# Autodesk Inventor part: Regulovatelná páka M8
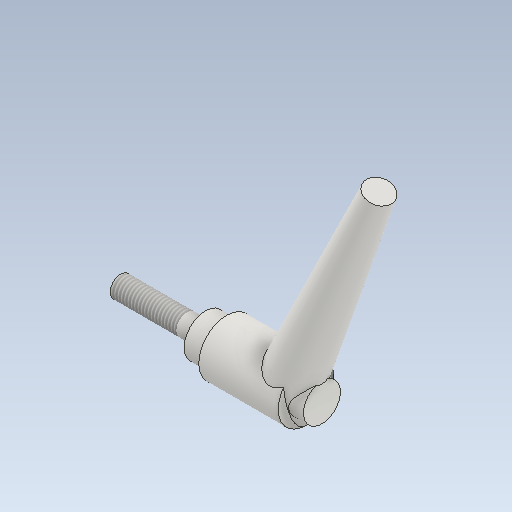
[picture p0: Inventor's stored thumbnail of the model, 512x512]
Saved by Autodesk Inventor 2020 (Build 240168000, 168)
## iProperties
Created: 2025-03
Part Number: Regulovatelná páka M8
Material: Ocel
Document SubType Name: Modeling
Designer: doma
Density: 7.85 g/cm^3
Appearance: Ocel
Mass: 212.296 g
Surface Area: 73.9458 cm^2
Volume: 27.0441 cm^3
Author: doma
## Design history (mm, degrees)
sketch "Náčrt1"
  geometry: L1 (0, 0)-(76, 0); L2 (0, 0)-(0, 4); L3 (0, 4)-(32, 4); L4 (32, 4)-(32, 8); L5 (32, 8)-(40, 8); L6 (40, 8)-(40, 10.5); L7 (40, 10.5)-(70, 10.5); L8 (70, 10.5)-(70, 7); L9 (70, 7)-(76, 7); L10 (76, 7)-(76, 0)
  constraints: 21 end point, 6 perpendicular, 3 vertical, 1 horizontal
  dimensions: "d0" = 4 distance of L1.start L2.end; "d1" = 32 distance of L2.end L3.end; "d2" = 8 distance of L4.end L5.end; "d3" = 8 distance between parallel lines of L1 L5; "d4" = 10.5 distance between parallel lines of L1 L7; "d5" = 36 distance between parallel lines of L10 L6; "d6" = 30 distance of L6.end L7.end; "d7" = 7 distance from line of L1.end L9
revolve "Rotace1" sketch "Náčrt1" stored, may be unused: angle "d8" = 90 deg
feature "Závit1" dims "d9" = 25, "d10" = 0
sketch "Náčrt2"
  geometry: L1 (70, -10.5)-(70, 10.5) reference; L2 (70, -10.5)-(102.211, 78); L3 (70, -10.5)-(164.18, -10.5); L4 (-34.225, 0)-(205.35, 0) reference; 1 further point
  constraints: 4 end point, 1 equal length, 1 horizontal
  dimensions: "d12" = 70 deg angle of L3 L2; "d13" = 78 distance from line of L2.end L4
node "Pracovní rovina2"
sketch "Náčrt3" dims "d14" = 10
  geometry: 5 further points
  constraints: 1 horizontal alignment, 2 other
node "Pracovní rovina3"
sketch "Náčrt4" dims "d15" = 20
  geometry: 3 further points
  constraints: 1 horizontal alignment, 2 other
feature "Šablonování1" sketch "Náčrt4" dims "d16" = 0, "d17" = 90 deg, "d18" = 0, "d19" = 90 deg, "d20" = 0, "d21" = 90 deg
sketch "Náčrt5"
  geometry: L1 (-10.5, 0)-(-33.185, -8.252); L2 (-33.185, -8.252)-(-11.332, -39.801); L3 (-11.332, -39.801)-(24.993, -30.829); L4 (24.993, -30.829)-(10.5, 0); A1 r 10.5 centre (0, 0) between (-8.489, 6.18) and (0, -10.5) reference; A2 r 10.5 centre (0, 0) between (0, -10.5) and (8.489, 6.18) reference; A3 r 10.5 centre (0, 0) between (-8.489, 6.18) and (0, -10.5) reference; 3 further points
  constraints: 8 end point, 2 point on circle
extrude "Vysunutí1" cut sketch "Náčrt5" distance "d22" = 33.75; taper "d23" = 0 deg
node "Těleso1"
